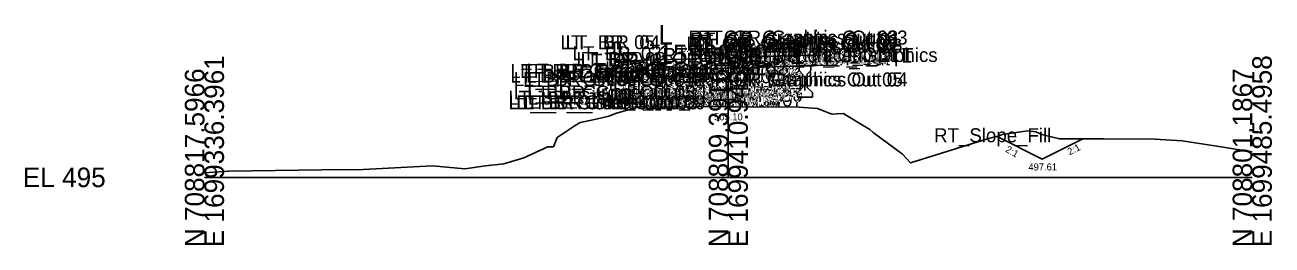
# Model space of a CAD drawing. Extents: x -63 to 1153, y -24 to 9522.
# Drawn here: x -25.7 to 152.8, y 6990.3 to 7021.8 of the extents above; entities that cross this region are included whole.
import ezdxf

# ---------------------------------------------------------------- set-up
doc = ezdxf.new("R2010")
doc.units = 0
for name, color, linetype in [('Default', 7, 'Continuous'), ('Exist Cross Section Cell', 7, 'Continuous'), ('Exist XS Center Line Elevation Label', 7, 'Continuous'), ('Exist XS Ground Line', 7, 'Continuous'), ('Prop CMT Concrete Structures', 7, 'Continuous'), ('Prop CMT DNC', 7, 'Continuous'), ('Prop CMT Slope Grass', 7, 'Continuous'), ('Prop XS DDE Earthwork Shape', 7, 'Continuous'), ('Prop XS Ditch Standard Text', 7, 'Continuous'), ('Prop XS SE Text', 7, 'Continuous'), ('Prop XS Side Slope Text', 7, 'Continuous')]:
    doc.layers.add(name, color=color, linetype=linetype)

msp = doc.modelspace()

# ---------------------------------------------------------------- linework, layer by layer
at = {"layer": 'Exist Cross Section Cell'}
for p, q in [((75, 7000), (75, 7019.02)), ((0, 7000), (75, 7000)), ((75, 7000), (150, 7000))]:
    msp.add_line(p, q, dxfattribs=at)
at = {"layer": 'Exist XS Ground Line'}
msp.add_lwpolyline([(0, 7000.64), (3.51, 7000.89), (16.82, 7001.07), (22.74, 7001.11), (32.64, 7001.65), (37.27, 7001.2), (40.25, 7001.64), (42.86, 7001.95), (45.74, 7002.8), (49.17, 7004.36), (49.97, 7004.35), (50.51, 7005.69), (53.09, 7007.43), (53.71, 7007.83), (54.05, 7007.89), (56.09, 7008.34), (57.91, 7008.74), (58.02, 7008.79), (58.85, 7009.16), (61.99, 7010.05), (70.19, 7010.11), (73.04, 7010.13), (75, 7010.1), (76.08, 7010.08), (85.08, 7010.03), (87.75, 7009.84), (89.44, 7009.17), (89.93, 7009.06), (90.54, 7009.1), (91.42, 7009.13), (91.56, 7009.11), (94.76, 7007.13), (95.26, 7006.83), (95.75, 7006.4), (99.92, 7003.32), (101.09, 7002.07), (112.09, 7005.5), (112.84, 7005.72), (113.78, 7005.95), (114.22, 7006.14), (117.9, 7006.64), (119.02, 7006.53), (119.9, 7006.15), (122.41, 7005.51), (128.76, 7005.54), (136.07, 7005.45), (139.99, 7005.21), (144.94, 7004.48), (150, 7003.64)], dxfattribs=at)
at = {"layer": 'Prop CMT Concrete Structures'}
for points in [[(75, 7017.13), (85, 7017.43), (87.59, 7017.51), (87.6, 7017.76), (88.18, 7018.59), (88.35, 7020.18), (89.09, 7020.18), (89.09, 7016.05)], [(75, 7017.13), (65.03, 7016.83), (60.22, 7016.69), (60.21, 7016.94), (59.63, 7017.77), (59.46, 7019.35), (58.72, 7019.35), (58.72, 7015.14)], [(75, 7015.63), (75, 7017.13)], [(58.72, 7015.14), (65.03, 7015.33), (75, 7015.63)], [(62.68, 7015.26), (61.85, 7015.24), (61.02, 7015.21)], [(61.02, 7015.21), (61.02, 7014.57)], [(61.02, 7014.57), (61.52, 7014.07)], [(62.18, 7014.07), (62.68, 7014.57)], [(62.68, 7014.57), (62.68, 7015.26)], [(75, 7015.63), (74.17, 7015.61)], [(74.17, 7015.61), (74.17, 7014.96)], [(74.17, 7014.96), (74.67, 7014.46)], [(89.09, 7016.05), (85, 7015.93), (75, 7015.63)], [(75, 7015.63), (75.83, 7015.66)], [(75, 7011.13), (75, 7015.63)], [(75, 7011.13), (75, 7015.63)], [(75.83, 7014.96), (75.33, 7014.46)], [(75.83, 7015.66), (75.83, 7014.96)], [(85.13, 7015.94), (85.97, 7015.96), (86.8, 7015.99)], [(85.13, 7015.29), (85.13, 7015.94)], [(85.63, 7014.79), (85.13, 7015.29)], [(85.63, 7012.88), (85.63, 7014.79)], [(86.8, 7015.29), (86.3, 7014.79)], [(86.3, 7014.79), (86.3, 7012.88)], [(86.8, 7015.99), (86.8, 7015.29)], [(61.52, 7014.07), (61.52, 7012.15)], [(62.18, 7012.15), (62.18, 7014.07)], [(74.67, 7014.46), (74.67, 7012.55)], [(75.33, 7014.46), (75.33, 7012.55)], [(84.88, 7012.13), (85.63, 7012.88)], [(86.3, 7012.88), (87.05, 7012.13)], [(61.52, 7012.15), (60.77, 7011.4)], [(60.77, 7011.4), (60.77, 7010.74)], [(62.93, 7011.4), (62.18, 7012.15)], [(62.93, 7010.74), (62.93, 7011.4)], [(74.67, 7012.55), (73.92, 7011.8)], [(73.92, 7011.8), (73.92, 7011.13)], [(73.92, 7011.13), (75, 7011.13)], [(76.08, 7011.13), (75, 7011.13)], [(75.33, 7012.55), (76.08, 7011.8)], [(76.08, 7011.8), (76.08, 7011.13)], [(84.88, 7011.46), (84.88, 7012.13)], [(87.05, 7011.46), (85.97, 7011.46), (84.88, 7011.46)], [(87.05, 7012.13), (87.05, 7011.46)], [(60.77, 7010.74), (61.85, 7010.74), (62.93, 7010.74)]]:
    msp.add_lwpolyline(points, dxfattribs=at)
at = {"layer": 'Prop CMT Slope Grass'}
for q in [(113.5, 7005.83), (125.77, 7005.53)]:
    msp.add_line((119.94, 7002.61), q, dxfattribs=at)
at = {"layer": 'Prop XS DDE Earthwork Shape'}
msp.add_lwpolyline([(113.5, 7005.83), (113.78, 7005.95), (114.22, 7006.14), (114.22, 7006.14), (117.9, 7006.64), (119.02, 7006.53), (119.9, 7006.15), (122.41, 7005.51), (125.77, 7005.53), (119.94, 7002.61)], close=True, dxfattribs=at)

# ---------------------------------------------------------------- texts
at = {"layer": 'Default'}
msp.add_text('-', height=0.0001, dxfattribs=at).set_placement((0, 7000))
at = {"layer": 'Exist Cross Section Cell'}
for s, p in [('L', (65, 7019.02)), ('15+68.00 / 1', (65, 7016.22)), ('EL 495', (-26, 6998.6))]:
    msp.add_text(s, height=2.8, dxfattribs=at).set_placement(p)
for s, p in [('E 1699336.3961', (2.8, 6990)), ('E 1699410.9459', (77.8, 6990)), ('E 1699485.4958', (152.8, 6990)), ('N 708817.5966', (0, 6990)), ('N 708809.3916', (75, 6990)), ('N 708801.1867', (150, 6990))]:
    msp.add_text(s, height=2.8, rotation=90, dxfattribs=at).set_placement(p)
at = {"layer": 'Exist XS Center Line Elevation Label'}
msp.add_text('505.10', height=1, dxfattribs=at).set_placement((72.97, 7008.17))
at = {"layer": 'Prop CMT DNC'}
for s, p in [('LT_ BR_05', (50.96, 7018.35)), ('LT_ BR_04', (51.7, 7018.35)), ('RT_GR_Graphics Out 08', (69.02, 7018.15)), ('RT_GR_Graphics Out 02', (69.29, 7019.02)), ('RT_GR_Graphics Out 09', (69.29, 7018.44)), ('RT_GR_Graphics Out 07', (69.29, 7017.85)), ('RT_GR_Graphics Out 01', (69.59, 7018.73)), ('RT_GR_Graphics Out 06', (69.91, 7017.85)), ('RT_GR_Graphics Out 03', (70.63, 7019.02)), ('LT_BR_03', (52.69, 7016.77)), ('RT_GS_OS_GR_Face_Graphics', (65.58, 7016.52)), ('PV1_PGL', (69.47, 7016.13)), ('RT_Sub_Trench_Out_DLT', (69.53, 7016.5)), ('RT_Sub_Trench_Out', (72.71, 7016.04)), ('RT_PS2_Shelf_Out', (74.25, 7016.28)), ('RT_PV1_OEOT', (75.69, 7016.43)), ('RT_PS2_OEOP', (78.5, 7016.28)), ('RT_PS1_OEOP', (78.83, 7016.52)), ('RT_GS_OS_CTL', (80.49, 7016.43)), ('LT_BR_Girder Out 01', (45.2, 7014.24)), ('LT_BR_Girder Out 14', (46.12, 7014.26)), ('LT_BR_02', (53.27, 7015.94)), ('LT_BR_01', (53.85, 7015.69)), ('LT_PV1_OEOT', (55.77, 7015.83)), ('LT_BR_Girder Mid 02', (57.35, 7014.61)), ('LT_BR_07', (58.09, 7014.33)), ('RT_BR_Girder Mid 02', (58.97, 7014.66)), ('BR_PGL', (69.83, 7014.63)), ('LT_BR_Girder Out 02', (43.8, 7014.21)), ('LT_BR_Girder Out 03', (43.8, 7013.57)), ('LT_BR_Girder Out 04', (44.3, 7013.07)), ('LT_BR_Girder Out 12', (45.62, 7013.07)), ('LT_BR_Girder Out 13', (46.12, 7013.57)), ('LT_BR_06', (51.73, 7014.14)), ('LT_BR_Girder Mid 03', (57.35, 7013.96)), ('LT_BR_Girder Mid 04', (57.85, 7013.46)), ('RT_BR_Girder Mid 04', (58.47, 7013.46)), ('RT_BR_Girder Mid 03', (58.97, 7013.96)), ('RT_GR_Graphics Out 05', (69.96, 7013.02)), ('RT_GR_Graphics Out 04', (70.63, 7013.02)), ('LT_BR_Girder Out 05', (44.3, 7011.15)), ('LT_BR_Girder Out 11', (46.18, 7011.15)), ('LT_BR_Girder Mid 06', (57.05, 7010.8)), ('LT_BR_Girder Mid 05', (57.85, 7011.55)), ('RT_BR_Girder Mid 05', (58.47, 7011.55)), ('RT_BR_Girder Mid 06', (59.17, 7010.8)), ('LT_BR_Girder Out 06', (43.51, 7010.4)), ('LT_BR_Girder Out 07', (43.55, 7009.74)), ('LT_BR_Girder Out 08', (44.64, 7009.74)), ('LT_BR_Girder Out 09', (45.72, 7009.74)), ('LT_BR_Girder Out 10', (46.29, 7010.4)), ('LT_BR_Girder Mid 07', (57.1, 7010.13)), ('RT_BR_Girder Mid 07', (59.22, 7010.13)), ('BR_Girder Mid 08', (60.87, 7010.13)), ('RT_Slope_Fill', (104.45, 7005.03))]:
    msp.add_text(s, height=2, dxfattribs=at).set_placement(p)
at = {"layer": 'Prop XS Ditch Standard Text'}
msp.add_text('497.61', height=1, dxfattribs=at).set_placement((117.96, 7000.99))
at = {"layer": 'Prop XS SE Text'}
for rotation, p in [(1.719, (68.24, 7017.93)), (1.7191, (78.22, 7018.23))]:
    msp.add_text('0.030', height=1, rotation=rotation, dxfattribs=at).set_placement(p)
at = {"layer": 'Prop XS Side Slope Text'}
for rotation, p in [(330.2424, (114.58, 7003.72)), (26.5651, (123.85, 7003.14))]:
    msp.add_text('2:1', height=1, rotation=rotation, dxfattribs=at).set_placement(p)

doc.saveas('drawing.dxf')
